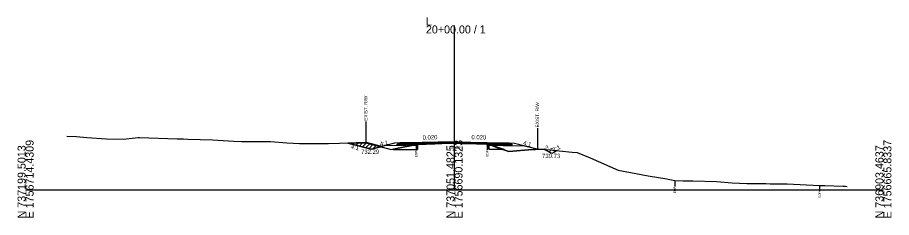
# Model space of a CAD drawing. Extents: x -26 to 4303, y -10 to 9577.
# Drawn here: x 997.2 to 1302.8, y -9.7 to 60.4 of the extents above; entities that cross this region are included whole.
import ezdxf

# ---------------------------------------------------------------- set-up
doc = ezdxf.new("R2010")
doc.units = 0
for name, color, linetype in [('Exist CMT Pavement', 7, 'Continuous'), ('Old_Level_10', 7, 'Continuous'), ('Old_Level_2', 7, 'Continuous'), ('Pattern 1', 7, 'Continuous'), ('Prop CMT Conc Surface', 7, 'Continuous'), ('Prop CMT Concrete Structures', 7, 'Continuous'), ('Prop CMT Concrete Wall', 7, 'Continuous'), ('Prop CMT Pvmt Course 1', 7, 'Continuous'), ('Prop CMT Pvmt Course 1 CG', 7, 'Continuous'), ('Prop CMT Pvmt Course 1 Wedge', 7, 'Continuous'), ('Prop CMT Pvmt Course 2', 7, 'Continuous'), ('Prop CMT Pvmt Course 2 Wedge', 7, 'Continuous'), ('Prop CMT Pvmt Course 3', 7, 'Continuous'), ('Prop CMT Pvmt Surface', 7, 'Continuous'), ('Prop CMT Pvmt Surface Shoulder', 7, 'Continuous'), ('Prop CMT Pvmt Wedge Surface 1', 7, 'Continuous'), ('Prop CMT Pvmt Wedge Surface 2', 7, 'Continuous'), ('Prop CMT Pvmt Wedge Surface 3', 7, 'Continuous'), ('Prop CMT Shld Paved Course 1', 7, 'Continuous'), ('Prop CMT Shld Paved Course 2', 7, 'Continuous'), ('Prop CMT Shld Paved Course 3', 7, 'Continuous'), ('Prop CMT Slope Grass', 7, 'Continuous'), ('Prop CMT Subgrade Earthwork', 7, 'Continuous'), ('Prop Road Sect_ Recs - UC Shallow (Outline)', 7, 'Continuous'), ('Prop Shade Light', 7, 'Continuous'), ('Prop XS DDE Elevations', 7, 'Continuous'), ('Prop XS Ditch Standard Text', 7, 'Continuous'), ('Prop XS Earthwork Shape', 7, 'Continuous'), ('Prop XS Hydro Elevations', 7, 'Continuous'), ('Prop XS SE Text', 7, 'Continuous'), ('Prop XS Side Slope Text', 7, 'Continuous'), ('Prop XS Wedging', 7, 'Continuous')]:
    doc.layers.add(name, color=color, linetype=linetype)

msp = doc.modelspace()

# ---------------------------------------------------------------- linework, layer by layer
at = {"layer": 'Exist CMT Pavement'}
for points in [[(1150, 16.83), (1133, 16.49)], [(1150, 16.83), (1167, 16.49)]]:
    msp.add_lwpolyline(points, dxfattribs=at)
at = {"layer": 'Old_Level_10'}
for p, q in [((1181.35, 14.09), (1179.35, 14.19)), ((1184.06, 12.73), (1181.35, 14.09)), ((1186.06, 13.73), (1184.06, 12.73))]:
    msp.add_line(p, q, dxfattribs=at)
at = {"layer": 'Old_Level_2'}
for p, q in [((1150, 0), (1150, 57.56)), ((1150, 0), (1150, 57.56)), ((1000, 0), (1150, 0)), ((1150, 0), (1300, 0)), ((1000, 0), (1150, 0)), ((1150, 0), (1300, 0))]:
    msp.add_line(p, q, dxfattribs=at)
at = {"layer": 'Pattern 1'}
for p, q in [((1113.33, 16.2), (1113.5, 16.37)), ((1114.46, 15.91), (1114.95, 16.4)), ((1115.59, 15.63), (1116.39, 16.42)), ((1116.73, 15.35), (1117.83, 16.45)), ((1117.86, 15.06), (1119.27, 16.48)), ((1118.99, 14.78), (1120.45, 16.24)), ((1120.12, 14.5), (1121.57, 15.95)), ((1121.42, 14.38), (1122.69, 15.66)), ((1123.31, 14.85), (1123.81, 15.36)), ((1162.12, 15.7), (1162.35, 15.93))]:
    msp.add_line(p, q, dxfattribs=at)
for points in [[(1121, 14.28), (1124.55, 15.17), (1119.54, 16.48), (1115.56, 16.41), (1112.7, 16.35)], [(1135.82, 15.66), (1137.08, 15.68), (1137.08, 15.85)], [(1161.97, 15.7), (1163, 15.68), (1162.03, 16.06), (1161.97, 16.06)]]:
    msp.add_lwpolyline(points, close=True, dxfattribs=at)
at = {"layer": 'Prop CMT Conc Surface'}
for points in [[(1136.58, 16.31), (1133, 16.24)], [(1133, 16.24), (1133, 16.03)], [(1133, 16.03), (1136.58, 16.1)], [(1136.58, 16.1), (1136.58, 16.31)], [(1161.46, 16.14), (1161.46, 16.35)], [(1161.46, 16.35), (1167, 16.24)], [(1167, 16.03), (1161.46, 16.14)], [(1167, 16.24), (1167, 16.03)]]:
    msp.add_lwpolyline(points, dxfattribs=at)
at = {"layer": 'Prop CMT Concrete Structures'}
for points in [[(1133, 16.24), (1133, 16.49)], [(1136.58, 16.31), (1133, 16.24)], [(1150, 16.7), (1136.58, 16.43)], [(1136.58, 16.43), (1136.58, 16.31)], [(1150, 16.7), (1161.46, 16.47)], [(1161.46, 16.47), (1161.46, 16.35)], [(1161.46, 16.35), (1167, 16.24)], [(1167, 16.24), (1167, 16.49)]]:
    msp.add_lwpolyline(points, dxfattribs=at)
at = {"layer": 'Prop CMT Pvmt Course 1'}
for points in [[(1136.58, 16.1), (1133, 16.03)], [(1133, 16.03), (1133, 15.69)], [(1133, 15.69), (1136.58, 15.77)], [(1136.58, 15.77), (1136.58, 16.1)], [(1161.46, 16.14), (1167, 16.03)], [(1161.46, 15.8), (1161.46, 16.14)], [(1167, 15.69), (1161.46, 15.8)], [(1167, 16.03), (1167, 15.69)]]:
    msp.add_lwpolyline(points, dxfattribs=at)
at = {"layer": 'Prop CMT Pvmt Course 1 Wedge'}
for points in [[(1136.58, 16.09), (1136.68, 16.09), (1137.19, 16.1), (1137.32, 16.1), (1137.63, 16.11), (1137.82, 16.11), (1138.15, 16.12), (1138.8, 16.13), (1140.1, 16.16), (1142.54, 16.21), (1142.64, 16.21), (1143.1, 16.22), (1145.17, 16.26), (1145.57, 16.27), (1147.23, 16.3)], [(1147.23, 16.3), (1145.57, 16.24), (1145.17, 16.22), (1143.1, 16.16), (1142.64, 16.15), (1142.54, 16.14), (1140.1, 16.03), (1138.8, 15.99), (1138.15, 15.97), (1137.82, 15.96), (1137.63, 15.95), (1137.32, 15.93), (1137.19, 15.93), (1136.68, 15.86), (1136.58, 15.85)], [(1136.58, 15.85), (1136.58, 16.09)], [(1161.46, 16.06), (1161.31, 16.07), (1161.22, 16.08), (1161.03, 16.09), (1160.37, 16.13), (1158.53, 16.16), (1157.84, 16.17), (1157.7, 16.17), (1155.3, 16.25), (1154.67, 16.25), (1152.77, 16.27), (1151.64, 16.31), (1150.24, 16.34), (1150.07, 16.35)], [(1150.07, 16.35), (1150.24, 16.35)], [(1150.24, 16.35), (1151.64, 16.32), (1152.77, 16.3), (1154.67, 16.26), (1155.3, 16.25), (1157.7, 16.2), (1157.84, 16.2), (1158.53, 16.18), (1160.37, 16.15), (1161.03, 16.13), (1161.22, 16.13), (1161.31, 16.13), (1161.46, 16.13)], [(1161.46, 16.13), (1161.46, 16.06)]]:
    msp.add_lwpolyline(points, dxfattribs=at)
at = {"layer": 'Prop CMT Pvmt Course 2'}
for points in [[(1133, 16.49), (1131, 16.45), (1130.74, 16.19)], [(1130.74, 16.19), (1133, 16.24)], [(1133, 16.24), (1133, 16.49)], [(1167, 16.49), (1169, 16.45), (1169.26, 16.19)], [(1167, 16.24), (1167, 16.49)], [(1169.26, 16.19), (1167, 16.24)]]:
    msp.add_lwpolyline(points, dxfattribs=at)
at = {"layer": 'Prop CMT Pvmt Course 2 Wedge'}
for points in [[(1131, 16.45), (1129, 16.29), (1121, 14.29), (1112.69, 16.36)], [(1169, 16.45), (1171, 16.29), (1179.39, 14.19)]]:
    msp.add_lwpolyline(points, dxfattribs=at)
at = {"layer": 'Prop CMT Pvmt Course 3'}
for points in [[(1133, 16.24), (1130.74, 16.19), (1130.53, 15.98)], [(1130.53, 15.98), (1133, 16.03)], [(1133, 16.03), (1133, 16.24)], [(1167, 16.24), (1169.26, 16.19), (1169.47, 15.98)], [(1167, 16.03), (1167, 16.24)], [(1169.47, 15.98), (1167, 16.03)]]:
    msp.add_lwpolyline(points, dxfattribs=at)
at = {"layer": 'Prop CMT Pvmt Surface'}
for points in [[(1150, 16.58), (1133, 16.24)], [(1133, 16.24), (1133, 16.49)], [(1150, 16.58), (1167, 16.24)], [(1167, 16.24), (1167, 16.49)]]:
    msp.add_lwpolyline(points, dxfattribs=at)
at = {"layer": 'Prop CMT Pvmt Surface Shoulder'}
for points in [[(1136.58, 15.85), (1136.68, 15.86), (1137.19, 15.93), (1137.32, 15.93), (1137.63, 15.95), (1137.82, 15.96), (1138.15, 15.97), (1138.8, 15.99), (1140.1, 16.03), (1142.54, 16.14), (1142.64, 16.15), (1143.1, 16.16), (1145.17, 16.22), (1145.57, 16.24), (1147.7, 16.32), (1148.18, 16.33), (1148.64, 16.34), (1149.21, 16.35), (1150, 16.35)], [(1150, 16.35), (1150.01, 16.35), (1150.05, 16.35), (1150.24, 16.34), (1151.64, 16.31), (1152.77, 16.27), (1154.67, 16.25), (1155.3, 16.25), (1157.7, 16.17), (1157.84, 16.17), (1158.53, 16.16), (1160.37, 16.13), (1161.03, 16.09), (1161.22, 16.08), (1161.31, 16.07), (1161.46, 16.06)]]:
    msp.add_lwpolyline(points, dxfattribs=at)
at = {"layer": 'Prop CMT Pvmt Wedge Surface 1'}
for p, q in [((1133.02, 15.57), (1125.53, 15.42)), ((1136.58, 15.64), (1133.02, 15.57)), ((1161.46, 15.68), (1166.98, 15.57)), ((1166.98, 15.57), (1174.47, 15.42))]:
    msp.add_line(p, q, dxfattribs=at)
for points in [[(1136.58, 15.64), (1136.58, 15.85)], [(1161.46, 15.68), (1161.46, 16.06)]]:
    msp.add_lwpolyline(points, dxfattribs=at)
at = {"layer": 'Prop CMT Pvmt Wedge Surface 2'}
for points in [[(1136.58, 16.43), (1136.68, 16.43), (1137.19, 16.44), (1137.32, 16.45), (1137.63, 16.45), (1137.82, 16.46), (1138.15, 16.46), (1138.8, 16.48), (1140.1, 16.5), (1142.54, 16.55), (1142.64, 16.55), (1143.1, 16.56), (1145.17, 16.6), (1145.57, 16.61), (1147.7, 16.65), (1148.18, 16.66), (1148.64, 16.67), (1149.21, 16.68), (1150, 16.7)], [(1150, 16.58), (1149.21, 16.56), (1148.64, 16.55), (1148.18, 16.54), (1147.7, 16.53), (1145.57, 16.49), (1145.17, 16.48), (1143.1, 16.44), (1142.64, 16.43), (1142.54, 16.43), (1140.1, 16.38), (1138.8, 16.35), (1138.15, 16.34), (1137.82, 16.33), (1137.63, 16.33), (1137.32, 16.32), (1137.19, 16.32), (1136.68, 16.31), (1136.58, 16.31)], [(1136.58, 16.31), (1136.58, 16.43)], [(1150, 16.7), (1150, 16.58)], [(1150, 16.7), (1150.01, 16.7), (1150.05, 16.7), (1150.24, 16.7), (1151.64, 16.67), (1152.77, 16.65), (1154.67, 16.61), (1155.3, 16.59), (1157.7, 16.55), (1157.84, 16.54), (1158.53, 16.53), (1160.37, 16.49), (1161.03, 16.48), (1161.22, 16.48), (1161.31, 16.47), (1161.46, 16.47)], [(1161.46, 16.35), (1161.31, 16.35), (1161.22, 16.35), (1161.03, 16.36), (1160.37, 16.37), (1158.53, 16.41), (1157.84, 16.42), (1157.7, 16.42), (1155.3, 16.47), (1154.67, 16.48), (1152.77, 16.52), (1151.64, 16.54), (1150.24, 16.57), (1150.05, 16.57), (1150.01, 16.58), (1150, 16.58)], [(1161.46, 16.47), (1161.46, 16.35)]]:
    msp.add_lwpolyline(points, dxfattribs=at)
at = {"layer": 'Prop CMT Pvmt Wedge Surface 3'}
for points in [[(1136.58, 16.31), (1136.68, 16.31), (1137.19, 16.32), (1137.32, 16.32), (1137.63, 16.33), (1137.82, 16.33), (1138.15, 16.34), (1138.8, 16.35), (1140.1, 16.38), (1142.54, 16.43), (1142.64, 16.43), (1143.1, 16.44), (1145.17, 16.48), (1145.57, 16.49), (1147.7, 16.53), (1148.18, 16.54), (1148.64, 16.55), (1149.21, 16.56), (1150, 16.58)], [(1150, 16.37), (1149.21, 16.37), (1148.64, 16.35), (1148.18, 16.34), (1147.7, 16.33), (1147.23, 16.31), (1145.57, 16.28), (1145.17, 16.27), (1143.1, 16.23), (1142.64, 16.22), (1142.54, 16.22), (1140.1, 16.17), (1138.8, 16.14), (1138.15, 16.13), (1137.82, 16.12), (1137.63, 16.12), (1137.32, 16.11), (1137.19, 16.11), (1136.68, 16.1), (1136.58, 16.1)], [(1136.58, 16.1), (1136.58, 16.31)], [(1150, 16.58), (1150, 16.37)], [(1150, 16.58), (1150.01, 16.58), (1150.05, 16.57), (1150.24, 16.57), (1151.64, 16.54), (1152.77, 16.52), (1154.67, 16.48), (1155.3, 16.47), (1157.7, 16.42), (1157.84, 16.42), (1158.53, 16.41), (1160.37, 16.37), (1161.03, 16.36), (1161.22, 16.35), (1161.31, 16.35), (1161.46, 16.35)], [(1161.46, 16.14), (1161.31, 16.14), (1161.22, 16.14), (1161.03, 16.15), (1160.37, 16.16), (1158.53, 16.2), (1157.84, 16.21), (1157.7, 16.21), (1155.3, 16.26), (1154.67, 16.27), (1152.77, 16.31), (1151.64, 16.33), (1150.24, 16.36), (1150.07, 16.37), (1150.05, 16.37), (1150.01, 16.37), (1150, 16.37)], [(1161.46, 16.35), (1161.46, 16.14)]]:
    msp.add_lwpolyline(points, dxfattribs=at)
at = {"layer": 'Prop CMT Shld Paved Course 1'}
for points in [[(1133, 16.03), (1133, 16.49)], [(1150, 16.37), (1133, 16.03)], [(1150, 16.37), (1167, 16.03)], [(1167, 16.03), (1167, 16.49)]]:
    msp.add_lwpolyline(points, dxfattribs=at)
at = {"layer": 'Prop CMT Shld Paved Course 2'}
for points in [[(1133, 16.49), (1131, 16.45)], [(1167, 16.49), (1169, 16.45)]]:
    msp.add_lwpolyline(points, dxfattribs=at)
at = {"layer": 'Prop CMT Shld Paved Course 3'}
for points in [[(1150, 16.83), (1133, 16.49)], [(1133, 16.49), (1133, 16.24)], [(1133, 16.24), (1136.58, 16.31)], [(1136.58, 16.43), (1150, 16.7)], [(1136.58, 16.31), (1136.58, 16.43)], [(1150, 16.83), (1167, 16.49)], [(1161.46, 16.47), (1150, 16.7)], [(1161.46, 16.35), (1161.46, 16.47)], [(1167, 16.24), (1161.46, 16.35)], [(1167, 16.49), (1167, 16.24)]]:
    msp.add_lwpolyline(points, dxfattribs=at)
at = {"layer": 'Prop CMT Slope Grass'}
msp.add_lwpolyline([(1014.42, 18.82), (1017.85, 18.67), (1021.4, 18.36), (1028.33, 17.81), (1034.08, 17.69), (1039.4, 18.34), (1039.82, 18.38), (1053, 17.9), (1055.23, 17.81), (1056.71, 17.77), (1065.37, 17.56), (1072.85, 17.07), (1075.5, 16.96), (1081.56, 16.89), (1085.64, 16.89), (1091.32, 16.42), (1095.77, 16.23), (1103.44, 16.27), (1105.91, 16.21), (1109.75, 16.31), (1119.03, 16.48), (1126.99, 14.39), (1127.79, 14.16), (1128.28, 14.26), (1132.31, 15.11), (1135, 15.61), (1136.68, 15.86), (1137.32, 15.93), (1137.82, 15.96), (1138.15, 15.97), (1138.8, 15.99), (1140.1, 16.03), (1142.64, 16.15), (1143.1, 16.16), (1145.17, 16.22), (1147.05, 16.29), (1147.7, 16.32), (1148.61, 16.34), (1149.21, 16.35), (1150.24, 16.34), (1151.64, 16.31), (1152.77, 16.27), (1154.67, 16.25), (1155.3, 16.25), (1157.84, 16.17), (1158.53, 16.16), (1160.37, 16.13), (1161.22, 16.08), (1161.52, 16.06), (1164.48, 14.91), (1168.98, 13.37), (1175.92, 13.99), (1180.8, 14.27), (1182, 14.15), (1191.19, 13.2), (1192.89, 13.09), (1197.39, 11.2), (1207.26, 6.85), (1217.73, 4.86), (1224.24, 3.81), (1224.75, 3.74), (1227.05, 3.25), (1230.02, 3.17), (1233.38, 3.11), (1241.62, 2.92), (1247.07, 2.45), (1252.19, 2.28), (1258.83, 2.2), (1260.44, 2.12), (1266.33, 2.06), (1277.68, 1.58), (1279.47, 1.51), (1285.91, 1.33), (1286.78, 1.3), (1287.3, 1.16)], dxfattribs=at)
at = {"layer": 'Prop CMT Subgrade Earthwork'}
for points in [[(1133, 16.03), (1130.53, 15.98), (1130.03, 15.97), (1129.69, 15.63)], [(1129.69, 15.63), (1133, 15.69)], [(1133, 15.69), (1133, 16.03)], [(1167, 16.03), (1169.47, 15.98), (1169.97, 15.97), (1170.31, 15.63)], [(1167, 15.69), (1167, 16.03)], [(1170.31, 15.63), (1167, 15.69)]]:
    msp.add_lwpolyline(points, dxfattribs=at)
at = {"layer": 'Prop Road Sect_ Recs - UC Shallow (Outline)'}
for points in [[(1137.08, 14.18), (1128.64, 14.02), (1128.63, 14.23), (1131.42, 14.81), (1135.05, 15.53), (1135.82, 15.66), (1137.08, 15.68)], [(1167.35, 14.1), (1161.97, 14.2), (1161.97, 15.7), (1163, 15.68), (1164.97, 14.92)]]:
    msp.add_lwpolyline(points, close=True, dxfattribs=at)
at = {"layer": 'Prop Shade Light'}
for points in [[(1137.08, 15.68), (1135.82, 15.66), (1135.05, 15.53), (1131.42, 14.81), (1128.63, 14.23), (1128.64, 14.02), (1137.08, 14.18), (1137.08, 15.68)], [(1137.08, 15.68), (1135.82, 15.66), (1135.05, 15.53), (1131.42, 14.81), (1128.63, 14.23), (1128.64, 14.02), (1137.08, 14.18), (1137.08, 15.68)], [(1164.97, 14.92), (1163, 15.68), (1161.97, 15.7), (1161.97, 14.2), (1167.35, 14.1), (1164.97, 14.92)]]:
    msp.add_lwpolyline(points, dxfattribs=at)
at = {"layer": 'Prop XS DDE Elevations'}
for points in [[(1112.69, 16.36), (1119.03, 16.48), (1124.28, 15.11), (1121, 14.29)], [(1125.53, 15.42), (1124.28, 15.11), (1126.99, 14.39), (1127.79, 14.16), (1128.28, 14.26), (1132.31, 15.11), (1134.97, 15.61), (1133.02, 15.57)], [(1134.97, 15.61), (1135, 15.61), (1136.58, 15.85), (1136.58, 15.64)], [(1136.68, 15.86), (1137.32, 15.93), (1137.19, 15.93)], [(1137.32, 15.93), (1137.82, 15.96), (1137.63, 15.95)], [(1140.1, 16.03), (1142.64, 16.15), (1142.54, 16.14)], [(1145.17, 16.22), (1147.05, 16.29), (1147.7, 16.32), (1145.57, 16.24)], [(1147.7, 16.32), (1148.61, 16.34), (1148.18, 16.33)], [(1148.61, 16.34), (1148.64, 16.34), (1149.21, 16.35)], [(1149.21, 16.35), (1150.24, 16.34), (1150.05, 16.35), (1150, 16.35)], [(1155.3, 16.25), (1157.84, 16.17), (1157.7, 16.17)], [(1160.37, 16.13), (1161.22, 16.08), (1161.03, 16.09)], [(1161.22, 16.08), (1161.46, 16.06), (1161.31, 16.07)], [(1161.46, 16.06), (1161.52, 16.06), (1162.56, 15.66), (1161.46, 15.68)], [(1174.47, 15.42), (1179.39, 14.19), (1175.92, 13.99), (1168.98, 13.37), (1164.48, 14.91), (1162.56, 15.66), (1166.98, 15.57)]]:
    msp.add_lwpolyline(points, close=True, dxfattribs=at)
at = {"layer": 'Prop XS Ditch Standard Text'}
for p, q in [((1118.97, 23.88), (1118.97, 16.48)), ((1178.97, 21.57), (1178.97, 14.16)), ((1136.58, 15.85), (1136.58, 13.8)), ((1161.46, 16.06), (1161.46, 14.01)), ((1227.05, 3.25), (1227.05, 1.2)), ((1277.68, 1.58), (1277.68, -0.47))]:
    msp.add_line(p, q, dxfattribs=at)
at = {"layer": 'Prop XS Earthwork Shape'}
msp.add_lwpolyline([(1181.35, 14.09), (1179.35, 14.19), (1180.8, 14.27), (1182, 14.15), (1186.06, 13.73), (1184.06, 12.73)], close=True, dxfattribs=at)
at = {"layer": 'Prop XS Wedging'}
for p, q in [((1150, 16.7), (1136.58, 16.43)), ((1136.58, 16.31), (1150, 16.58)), ((1136.58, 16.31), (1150, 16.58)), ((1136.58, 16.43), (1136.58, 16.31)), ((1136.58, 16.31), (1136.58, 16.1)), ((1136.58, 16.1), (1136.58, 15.86)), ((1136.58, 15.86), (1136.58, 15.85)), ((1161.46, 16.47), (1150, 16.7)), ((1161.46, 16.35), (1150, 16.58)), ((1150, 16.58), (1161.46, 16.35)), ((1150, 16.58), (1150, 16.58)), ((1161.46, 16.35), (1161.46, 16.47)), ((1161.46, 16.14), (1161.46, 16.35)), ((1161.46, 16.08), (1161.46, 16.14))]:
    msp.add_line(p, q, dxfattribs=at)
for points in [[(1150, 16.58), (1150, 16.58), (1136.58, 16.31)], [(1136.58, 15.85), (1136.68, 15.86), (1137.32, 15.93), (1137.82, 15.96), (1138.15, 15.97), (1138.8, 15.99), (1140.1, 16.03), (1142.64, 16.15), (1143.1, 16.16), (1145.17, 16.22), (1147.05, 16.29), (1147.7, 16.32), (1148.61, 16.34), (1149.21, 16.35), (1150.24, 16.34), (1151.64, 16.31), (1152.77, 16.27), (1154.67, 16.25), (1155.3, 16.25), (1157.84, 16.17), (1158.53, 16.16), (1160.37, 16.13), (1161.22, 16.08), (1161.46, 16.06)], [(1136.58, 15.86), (1136.58, 15.86)], [(1161.46, 16.35), (1150, 16.58), (1150, 16.58)], [(1161.46, 16.06), (1161.46, 16.06), (1161.46, 16.08)], [(1161.46, 16.08), (1161.46, 16.08)]]:
    msp.add_lwpolyline(points, dxfattribs=at)

# ---------------------------------------------------------------- texts
at = {"layer": 'Old_Level_2'}
for s, p in [('L', (1140, 57.56)), ('L', (1140, 57.56)), ('20+00.00 / 1', (1140, 54.76)), ('20+00.00 / 1', (1140, 54.76))]:
    msp.add_text(s, height=2.8, dxfattribs=at).set_placement(p)
for s, p in [('N 737199.5013', (1000, -10)), ('N 737199.5013', (1000, -10)), ('E 1756714.4309', (1002.8, -10)), ('E 1756714.4309', (1002.8, -10)), ('N 737051.4825', (1150, -10)), ('N 737051.4825', (1150, -10)), ('E 1756690.1323', (1152.8, -10)), ('E 1756690.1323', (1152.8, -10)), ('N 736903.4637', (1300, -10)), ('N 736903.4637', (1300, -10)), ('E 1756665.8337', (1302.8, -10)), ('E 1756665.8337', (1302.8, -10))]:
    msp.add_text(s, height=2.8, rotation=90, dxfattribs=at).set_placement(p)
at = {"layer": 'Prop CMT Concrete Wall'}
for rotation, p in [(334.1383, (1181.21, 14.31)), (25.8617, (1184.64, 13.23))]:
    msp.add_text('2:1', height=1.5, rotation=rotation, dxfattribs=at).set_placement(p)
msp.add_text('730.73', height=1.5, dxfattribs=at).set_placement((1180.62, 11.14))
at = {"layer": 'Prop CMT Pvmt Course 1 CG'}
msp.add_text('734.35', height=1, dxfattribs=at).set_placement((1147.87, 14.35))
at = {"layer": 'Prop XS Ditch Standard Text'}
for s, height, p in [('EXIST. R/W', 1.181, (1119.56, 24.19)), ('EXIST. R/W', 1.181, (1179.57, 21.87)), ('EOP', 0.787, (1136.97, 11.4)), ('EOP', 0.787, (1161.86, 11.61)), ('EOP', 0.787, (1227.44, -1.2)), ('EOP', 0.787, (1278.08, -2.87))]:
    msp.add_text(s, height=height, rotation=90, dxfattribs=at).set_placement(p)
at = {"layer": 'Prop XS Hydro Elevations'}
msp.add_text('732.29', height=1.5, dxfattribs=at).set_placement((1117.31, 12.61))
at = {"layer": 'Prop XS SE Text'}
for rotation, p in [(1.1458, (1138.86, 17.6)), (358.8542, (1155.9, 17.71))]:
    msp.add_text('0.020', height=1.5, rotation=rotation, dxfattribs=at).set_placement(p)
at = {"layer": 'Prop XS Side Slope Text'}
for rotation, p in [(345.9638, (1113.61, 14.51)), (14.0362, (1124.12, 15.25)), (345.9638, (1173.88, 15.74))]:
    msp.add_text('4:1', height=1.5, rotation=rotation, dxfattribs=at).set_placement(p)

doc.saveas('drawing.dxf')
